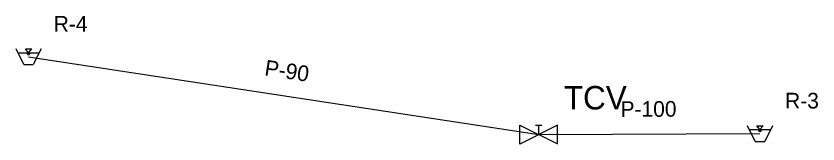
# Model space of a CAD drawing. Extents: x 130 to 385, y 111 to 152.
import ezdxf

# ---------------------------------------------------------------- set-up
doc = ezdxf.new("R2010")
doc.units = 0
doc.layers.add('Default', color=7, linetype='Continuous')

# ---------------------------------------------------------------- blocks, each defined once
blk = doc.blocks.new('TCV')
at = {"layer": 'Default'}
for p, q in [((-3, -1.5), (-3, 1.5)), ((-3, 1.5), (3, -1.5)), ((3, 1.5), (-3, -1.5)), ((-0.5, 1.5), (0.5, 1.5)), ((0, 0), (0, 1.5)), ((3, -1.5), (3, 1.5))]:
    blk.add_line(p, q, dxfattribs=at)
blk = doc.blocks.new('reservoir')
at = {"layer": 'Default'}
for p, q in [((-1.5, -2.5), (-4, 2.5)), ((-3.37, 1.25), (3.37, 1.25)), ((-1, 2.5), (1, 2.5)), ((0, 1.25), (-1, 2.5)), ((-0.53, 1), (0.53, 1)), ((-0.33, 0.75), (0.33, 0.75)), ((0, 1.25), (1, 2.5)), ((4, 2.5), (1.5, -2.5)), ((-1.5, -2.5), (1.5, -2.5))]:
    blk.add_line(p, q, dxfattribs=at)

msp = doc.modelspace()

# ---------------------------------------------------------------- linework, layer by layer
at = {"layer": 'Default'}
for points in [[(133.58, 139.2), (296.16, 114.35)], [(296.16, 114.35), (366.67, 114.67)]]:
    msp.add_lwpolyline(points, dxfattribs=at)

# ---------------------------------------------------------------- block references
for p in [(133.58, 139.2), (366.67, 114.67)]:
    msp.add_blockref('reservoir', p, dxfattribs=at)
at = {"layer": 'Default', "xscale": 2, "yscale": 2, "rotation": 0.25871854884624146}
msp.add_blockref('TCV', (296.16, 114.35), dxfattribs=at)

# ---------------------------------------------------------------- texts
at = {"layer": 'Default'}
for s, height, p in [('R-4', 5, (141.58, 147.2)), ('TCV', 7.5, (304.16, 122.35)), ('R-3', 5, (374.67, 122.67))]:
    msp.add_text(s, height=height, dxfattribs=at).set_placement(p)
for s, rotation, p in [('P-90', 351.3108, (208.57, 133.3)), ('P-100', 0.2587, (322.24, 119.97))]:
    msp.add_text(s, height=5, rotation=rotation, dxfattribs=at).set_placement(p)

doc.saveas('drawing.dxf')
